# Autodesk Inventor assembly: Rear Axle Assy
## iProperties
Length Units: 11269
Angle Units: 11279
Time Units: 11290
Mass Units: 11283
Shininess: 3
Angle Display Precision: 2
Document Length Units: 11269
Document Angle Units: 11279
Document Time Units: 11290
Document Mass Units: 11283
Document Length Units Precision: 3
Document Angle Units Precision: 2
Compacted: True
Created: 2001-08
Part Number: Rear Axle Assy
Document SubType Name: Assembly
Designer: Martin Budgell
Density: 0.0
Volumn: 0.0
Area: 0.0
PropertySet Name: Model Information
Control State: 0
Master: False
Checked Out: False
Author: Martin Budgell
